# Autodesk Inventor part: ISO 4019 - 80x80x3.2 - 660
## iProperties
Created: 2007-05
Part Number: ISO 4019 - 80x80x3.2 - 660
Material: Steel, Mild
Description: Cold-Finished Hollow Section
Vendor: Autodesk Inc.
Document SubType Name: Modeling
Standard: ISO 4019
Designer: kurs1
Standards Organization: ISO
Language: en-US
Size Designation: 80x80x3.2 - 660
Categories: <MemberInstance Version="R10.0.0"><Categories><Category DisplayName="Steel Shapes" InternalName="089c4875-fa83-4c05-b084-43b9cc11f5ed" Mnemonic="GRDR"><Category
Stock Number: 80x80x3.2
Density: 1 g/cm^3
G_L: 660,000 mm
Author: kurs1
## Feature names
1. Body [Extrusion]
2. Fillet1
3. Fillet2
